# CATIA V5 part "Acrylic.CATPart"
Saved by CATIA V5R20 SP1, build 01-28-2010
Part number: Acrylic
Bounding box of the stored display mesh (mm): x 0 to 183, y 0 to 180, z 0 to 3
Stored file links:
  C:\Users\elisf\Desktop\Elis\ENSINOFATEC\MAV5\DIP\Labirinto\RealBox\Acrylic.CATPart
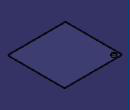
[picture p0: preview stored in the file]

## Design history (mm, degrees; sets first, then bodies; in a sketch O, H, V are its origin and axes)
Body1 (main body)
  Sketch1 on xy-plane, origin (0, 0, 0), H (1, 0, 0), V (0, 1, 0)
    line L1 (0, 0) -> (183, 0)
    line L2 (183, 0) -> (183, 180)
    line L3 (183, 180) -> (0, 180)
    line L4 (0, 180) -> (0, 0)
    length L4 = 180
    length L1 = 183
    horizontal: L1 H, L3 H
    vertical: L2 V, L4 V
  Pad1: profile Sketch1, direction (0, 0, 1), length 3
  Sketch2 on end face of Pad1, origin (0, 0, 3), H (1, 0, 0), V (0, 1, 0)
    reference projected line E1 (183, 180) -> (0, 180) from edge [face of Pad1 from Sketch1.L3 | end face of Pad1]
    reference projected line E2 (0, 180) -> (0, 0) from edge [face of Pad1 from Sketch1.L4 | end face of Pad1]
    construction line L1 (13.75, 180) -> (13.75, 167)
    point P5 (13.75, 180)
    circle A1 centre (13.75, 167) radius 7.5
    length L1 = 13
    distance L1 E2 = 13.75
    radius A1 = 7.5
    coincidence: P5 E1
    vertical: L1 V
  Pocket1: profile Sketch2, direction (0, 0, -1), length 3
